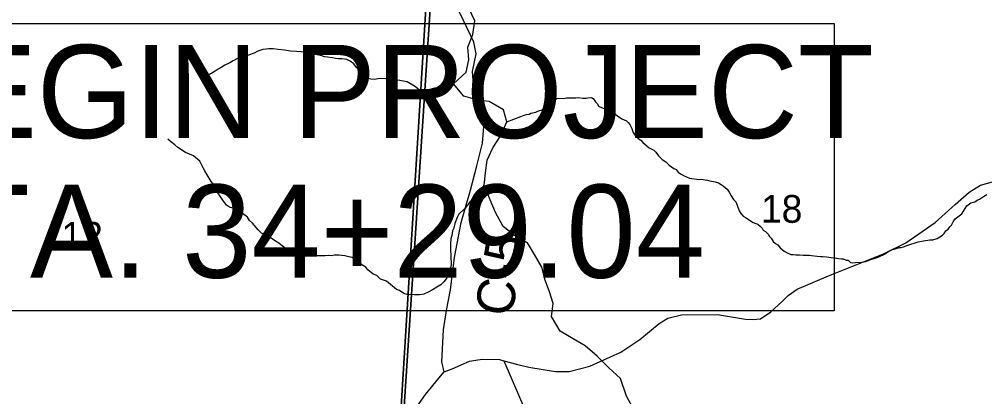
# Model space of a CAD drawing. Extents: x 0 to 34, y 0 to 22.
# Drawn here: x 6.132 to 7.584, y 17.554 to 18.121 of the extents above; entities that cross this region are included whole.
import ezdxf

# ---------------------------------------------------------------- set-up
doc = ezdxf.new("R2010")
doc.units = 0
for name, color, linetype in [('GM_X_Corporation', 7, 'Continuous'), ('GM_X_County_Road', 7, 'Continuous'), ('GM_X_County_Road_Text', 7, 'Continuous'), ('GM_X_Minor_River', 7, 'Continuous'), ('GM_X_Section_Text', 7, 'Continuous'), ('GM_X_State_Route', 7, 'Continuous'), ('SH_Masking', 7, 'Continuous'), ('SH_Text', 7, 'Continuous')]:
    doc.layers.add(name, color=color, linetype=linetype)

msp = doc.modelspace()

# ---------------------------------------------------------------- linework, layer by layer
at = {"layer": 'GM_X_Corporation'}
for points in [[(8.9, 16.2015), (8.9, 20.2763), (8.59, 20.3005), (8.3805, 20.3169), (8.0028, 20.34), (6.9032, 20.4198), (6.8961, 20.3303), (6.835, 19.4037), (6.824, 19.3005), (6.7876, 18.7583), (6.7629, 18.3924), (6.7536, 18.2991), (6.7043, 17.4985), (6.6962, 17.3669), (6.6852, 17.2401), (6.6249, 16.3344), (7.5782, 16.28), (7.7162, 16.2721), (7.873, 16.2628)], [(6.7676, 18.3985), (7.864, 18.3242), (7.7921, 17.3025), (6.6999, 17.3699), (6.7615, 18.3053)], [(5.775, 18.3681), (6.7615, 18.3053), (6.6999, 17.3699), (6.6918, 17.2464), (5.6845, 17.321)]]:
    msp.add_lwpolyline(points, close=True, dxfattribs=at)
msp.add_lwpolyline([(6.7043, 17.4985), (6.7536, 18.2991), (6.7629, 18.3924), (6.7876, 18.7583), (6.824, 19.3005), (6.5423, 19.3229), (5.9419, 19.3649), (5.6539, 19.3859), (5.0201, 19.4401), (4.8375, 19.4557), (3.8692, 19.5228), (3.8201, 19.5262), (3.0215, 19.5789), (2.5886, 19.6074), (2.105, 19.6393), (2.1, 19.6396), (2.1, 16.1353)], dxfattribs=at)
at = {"layer": 'GM_X_County_Road'}
for points in [[(6.7715, 17.5908), (6.7678, 17.6061), (6.7702, 17.654), (6.7747, 17.6833), (6.7808, 17.7144), (6.787, 17.7627), (6.7969, 17.8155), (6.811, 17.8642), (6.8205, 17.9003), (6.8289, 17.9345), (6.8308, 17.9596), (6.8225, 17.9931), (6.8153, 18.0227), (6.8141, 18.0421), (6.8195, 18.0691), (6.8161, 18.0866), (6.8001, 18.1189), (6.7846, 18.1516)], [(6.861, 17.6075), (6.8924, 17.5342), (6.8792, 17.482), (6.8648, 17.429), (6.8828, 17.4128), (6.909, 17.4016)]]:
    msp.add_lwpolyline(points, dxfattribs=at)
at = {"layer": 'GM_X_Minor_River'}
for points in [[(7.0572, 17.5332), (7.0452, 17.5545), (7.0362, 17.5811), (7.0188, 17.5971), (7.0015, 17.6146), (6.9834, 17.6298), (6.9652, 17.6405), (6.9456, 17.6519), (6.9328, 17.674), (6.9351, 17.6937), (6.9299, 17.7112), (6.9231, 17.7287), (6.9179, 17.7484), (6.9073, 17.7675), (6.8968, 17.7849), (6.8786, 17.7949), (6.8598, 17.8093), (6.8485, 17.8306), (6.8402, 17.8496), (6.8312, 17.8717), (6.8335, 17.8899), (6.8358, 17.9089), (6.8442, 17.9278), (6.8564, 17.946), (6.8655, 17.9665), (6.8603, 17.9847), (6.8391, 17.997), (6.8217, 17.9993), (6.8006, 18.0054), (6.7855, 18.0237), (6.8044, 18.0411), (6.8083, 18.0601), (6.8068, 18.0791), (6.8145, 18.098), (6.8176, 18.1185), (6.8085, 18.1375)], [(6.7855, 18.0237), (6.7706, 18.0212), (6.7652, 18.0187), (6.7607, 18.0176), (6.7565, 18.0173), (6.7497, 18.0155), (6.7387, 18.0149), (6.7337, 18.0146), (6.7266, 18.0205), (6.7158, 18.0267), (6.7044, 18.0288), (6.6969, 18.0293), (6.6912, 18.0302), (6.6836, 18.0311), (6.6765, 18.0316), (6.6715, 18.0313), (6.6666, 18.0302), (6.6609, 18.0307), (6.6568, 18.0319), (6.6519, 18.0377), (6.6445, 18.0435), (6.6396, 18.0482), (6.6356, 18.0536), (6.6299, 18.0579), (6.6247, 18.0606), (6.6175, 18.0615), (6.6122, 18.0616), (6.608, 18.062), (6.6035, 18.0629), (6.596, 18.0638), (6.5914, 18.0646), (6.5873, 18.0658), (6.5801, 18.0675), (6.576, 18.0687), (6.5677, 18.0703), (6.5631, 18.0708), (6.5563, 18.0717), (6.5491, 18.0722), (6.5401, 18.0731), (6.531, 18.0744), (6.5219, 18.0753), (6.514, 18.0762), (6.5075, 18.0763), (6.5034, 18.076), (6.4984, 18.0753), (6.4912, 18.0731), (6.4855, 18.0698), (6.4771, 18.0669), (6.4695, 18.0655), (6.4645, 18.0641), (6.4603, 18.0619), (6.4542, 18.0586), (6.4488, 18.0552), (6.4416, 18.0516), (6.4358, 18.0482), (6.4313, 18.046), (6.4267, 18.0427), (6.4221, 18.0397), (6.4148, 18.0364), (6.4146, 18.0364)], [(6.8655, 17.9665), (6.8864, 17.9748), (6.8918, 17.9766), (6.8952, 17.9777), (6.899, 17.9784), (6.9017, 17.9795), (6.9089, 17.9812), (6.9123, 17.9827), (6.9188, 17.9849), (6.925, 17.9909), (6.9338, 17.996), (6.938, 17.9994), (6.9411, 18.002), (6.9513, 18.0018), (6.9551, 18.0025), (6.9608, 18.0028), (6.9691, 18.0027), (6.9733, 18.003), (6.9797, 18.0021), (6.9846, 18.0024), (6.9873, 18.0027), (6.9926, 18.003), (6.9952, 18.0018), (6.9989, 17.9965), (7.0019, 17.9937), (7.0034, 17.9903), (7.009, 17.9875), (7.015, 17.9859), (7.018, 17.984), (7.024, 17.9804), (7.0282, 17.9781), (7.0319, 17.9757), (7.0383, 17.9711), (7.0454, 17.9683), (7.048, 17.9656), (7.0506, 17.9625), (7.0535, 17.9567), (7.0553, 17.9506), (7.0583, 17.946), (7.0631, 17.9417), (7.0672, 17.939), (7.0702, 17.9355), (7.0732, 17.9332), (7.0795, 17.9274), (7.0863, 17.9242), (7.0897, 17.9211), (7.0933, 17.9158), (7.0989, 17.91), (7.1045, 17.9064), (7.1072, 17.9041), (7.1094, 17.9014), (7.1165, 17.8964), (7.1203, 17.8948), (7.1232, 17.8909), (7.1266, 17.8886), (7.1311, 17.8858), (7.1401, 17.8819), (7.1435, 17.8815), (7.1511, 17.8806), (7.1605, 17.88), (7.1635, 17.8796), (7.1673, 17.8788), (7.1707, 17.8779), (7.1786, 17.8763), (7.1839, 17.8751), (7.1877, 17.8727), (7.191, 17.8704), (7.197, 17.8653), (7.2, 17.8611), (7.2029, 17.8553), (7.2062, 17.85), (7.2096, 17.8465), (7.2117, 17.8415), (7.2146, 17.8331), (7.2172, 17.8289), (7.2209, 17.825), (7.2254, 17.8223), (7.2303, 17.8188), (7.2359, 17.8156), (7.2397, 17.814), (7.2427, 17.8129), (7.2468, 17.8094), (7.2494, 17.8067), (7.2509, 17.804), (7.2542, 17.802), (7.2587, 17.7974), (7.2602, 17.7947), (7.2628, 17.7916), (7.2661, 17.787), (7.2694, 17.7839), (7.2732, 17.7819), (7.2765, 17.7773), (7.2795, 17.7746), (7.2825, 17.7723), (7.287, 17.7699)], [(6.881, 17.9721), (6.8809, 17.9721)], [(6.8312, 17.8717), (6.8208, 17.8577), (6.8158, 17.8536), (6.8107, 17.8472), (6.8022, 17.8363), (6.7933, 17.8281), (6.7906, 17.8228), (6.7874, 17.8141), (6.7858, 17.8069), (6.7838, 17.8028), (6.7829, 17.7956), (6.7813, 17.791), (6.7808, 17.7834), (6.7806, 17.7724), (6.7813, 17.7678), (6.7812, 17.7606), (6.7819, 17.7564), (6.7818, 17.7515), (6.7805, 17.7454), (6.7793, 17.7401), (6.7754, 17.7322), (6.7711, 17.7266), (6.7661, 17.7217), (6.7604, 17.718), (6.7538, 17.7143), (6.747, 17.7106), (6.7405, 17.7077), (6.7344, 17.7066), (6.7268, 17.7068), (6.7155, 17.7073), (6.7106, 17.7086), (6.7042, 17.7132), (6.6997, 17.7148), (6.6907, 17.7222), (6.6844, 17.7273), (6.6757, 17.7301), (6.6701, 17.7355), (6.6645, 17.7379), (6.6566, 17.7441), (6.6533, 17.7483), (6.6477, 17.7518), (6.6413, 17.7569), (6.6327, 17.7627), (6.6278, 17.7636), (6.6218, 17.7652), (6.6127, 17.7665), (6.6063, 17.7662), (6.6021, 17.7655), (6.5972, 17.7656), (6.5922, 17.7653), (6.5801, 17.7655), (6.5699, 17.7653), (6.562, 17.7658), (6.5559, 17.7671), (6.5484, 17.7691), (6.539, 17.7727), (6.5333, 17.7758), (6.5225, 17.7844), (6.5176, 17.7871), (6.5083, 17.7938), (6.5034, 17.7961), (6.4966, 17.7993), (6.4918, 17.8043), (6.4829, 17.8143), (6.4784, 17.8182), (6.4755, 17.8232), (6.468, 17.8287), (6.4616, 17.8318), (6.4534, 17.8369), (6.4485, 17.8385), (6.444, 17.8412), (6.4384, 17.8489), (6.4344, 17.8551), (6.431, 17.8597), (6.4277, 17.8655), (6.4259, 17.8712), (6.4211, 17.877), (6.4178, 17.882), (6.4148, 17.887), (6.4112, 17.8928), (6.409, 17.8977), (6.4038, 17.9073), (6.3945, 17.9155), (6.3825, 17.9206), (6.3709, 17.928), (6.3664, 17.9323), (6.36, 17.9373), (6.3559, 17.9408)], [(7.287, 17.7699), (7.2923, 17.7675), (7.296, 17.7675), (7.2998, 17.7666), (7.3055, 17.7669), (7.3112, 17.7664), (7.3203, 17.7663), (7.3237, 17.7659), (7.332, 17.765), (7.3369, 17.7645), (7.3403, 17.7641), (7.346, 17.7636), (7.3498, 17.7631), (7.3532, 17.7627), (7.3581, 17.7622), (7.3615, 17.7618), (7.3641, 17.7614), (7.3687, 17.7609), (7.3713, 17.7605), (7.3758, 17.7589), (7.3788, 17.7585), (7.3822, 17.7554), (7.3856, 17.7549), (7.3894, 17.7552), (7.3989, 17.7558), (7.4023, 17.7562), (7.4053, 17.7569), (7.4126, 17.7598), (7.4209, 17.7623), (7.424, 17.7634), (7.4278, 17.7652), (7.4305, 17.7663), (7.4335, 17.7678), (7.4362, 17.77), (7.4393, 17.7719), (7.4454, 17.7748), (7.4492, 17.7759), (7.4557, 17.7777), (7.4583, 17.778), (7.4621, 17.7787), (7.4686, 17.7813), (7.4839, 17.7863), (7.4945, 17.7884), (7.4987, 17.7887), (7.5017, 17.7891), (7.5059, 17.7894), (7.5124, 17.7912), (7.5204, 17.7964), (7.5231, 17.799), (7.5254, 17.8027), (7.5289, 17.8053), (7.5316, 17.8087), (7.5339, 17.8113), (7.5367, 17.8166), (7.5398, 17.8211), (7.5497, 17.8282), (7.5572, 17.8402), (7.5633, 17.8447), (7.569, 17.8465), (7.5728, 17.8487), (7.5763, 17.8505), (7.5824, 17.8546), (7.5874, 17.8576)]]:
    msp.add_lwpolyline(points, dxfattribs=at)
at = {"layer": 'GM_X_State_Route'}
for points in [[(6.8802, 17.6025), (6.8985, 17.5977), (6.9386, 17.5916), (6.9594, 17.5913), (6.9902, 17.5993), (7.037, 17.6204), (7.0653, 17.6395), (7.0944, 17.6634), (7.1074, 17.6717), (7.1279, 17.6764), (7.1824, 17.6769), (7.2244, 17.6699), (7.2358, 17.6694), (7.2468, 17.6708), (7.2624, 17.6809), (7.2793, 17.6966), (7.2885, 17.7057), (7.3022, 17.7154), (7.3494, 17.735), (7.4317, 17.7682), (7.4656, 17.7849), (7.5095, 17.8155), (7.5398, 17.8425), (7.5605, 17.8612), (7.5776, 17.8717), (7.6084, 17.8801)], [(6.7715, 17.5908), (6.7833, 17.5956), (6.8096, 17.6067), (6.8282, 17.6099), (6.8543, 17.6092), (6.861, 17.6075), (6.8706, 17.605), (6.8802, 17.6025)], [(6.7126, 17.5133), (6.7434, 17.557), (6.7634, 17.5814), (6.7715, 17.5908)]]:
    msp.add_lwpolyline(points, dxfattribs=at)
at = {"layer": 'SH_Masking'}
msp.add_lwpolyline([(5.8902, 18.1147), (7.3577, 18.1147), (7.3577, 17.6825), (5.8902, 17.6825)], close=True, dxfattribs=at)
at = {"layer": 'SH_Text'}
msp.add_lwpolyline([(5.8902, 18.1147), (7.3577, 18.1147), (7.3577, 17.6825), (5.8902, 17.6825)], close=True, dxfattribs=at)

# ---------------------------------------------------------------- texts
at = {"layer": 'GM_X_County_Road_Text'}
msp.add_text('C-5', height=0.05682, rotation=80.621, dxfattribs=at).set_placement((6.873, 17.672))
at = {"layer": 'GM_X_Section_Text'}
for s, p in [('18', (7.2476, 17.8149)), ('12', (6.1959, 17.7744))]:
    msp.add_text(s, height=0.04186, rotation=0, dxfattribs=at).set_placement(p)
at = {"layer": 'SH_Text'}
for s, p in [('BEGIN PROJECT', (5.9092, 17.9423)), ('STA. 34+29.04', (5.9092, 17.7323))]:
    msp.add_text(s, height=0.14, dxfattribs=at).set_placement(p)

doc.saveas('drawing.dxf')
